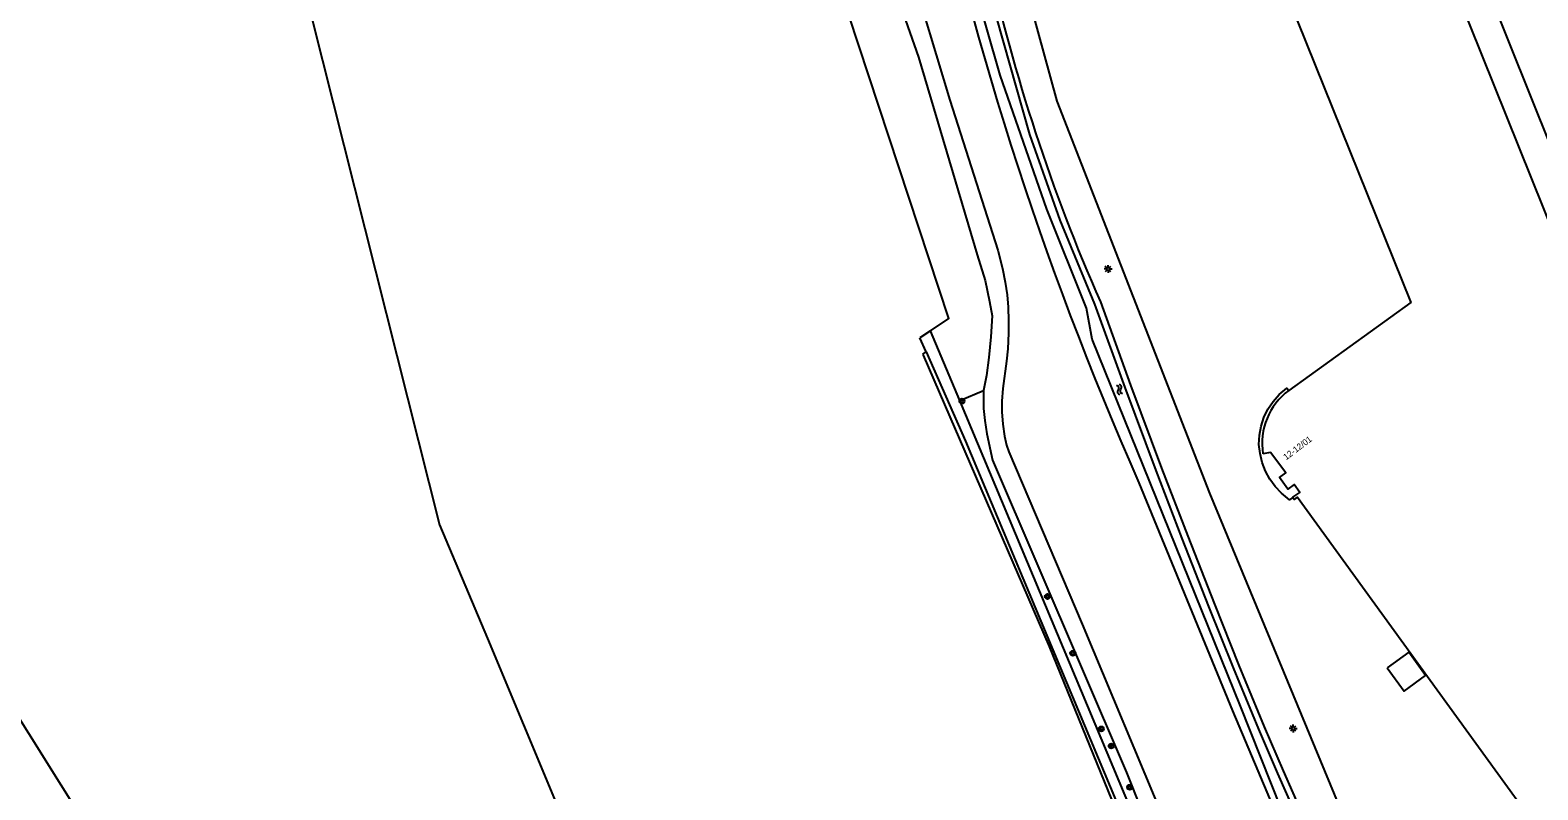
# Model space of a CAD drawing. Extents: x 126000 to 131009, y 393000 to 395500.
# Drawn here: x 130201.2 to 130441.7, y 393811.3 to 393932.5 of the extents above; entities that cross this region are included whole.
import ezdxf

# ---------------------------------------------------------------- set-up
doc = ezdxf.new("R2010")
doc.units = 0
for name, color, linetype in [('gg-afsc-hekwerk', 7, 'Continuous'), ('gg-anno-huisnummerreeks BGT', 7, 'Continuous'), ('gg-bbg-hoofdgebouw', 7, 'Continuous'), ('gg-bbg-luifel en loopbrug', 7, 'Continuous'), ('gg-bbg-onder overbouw', 7, 'Continuous'), ('gg-bbg-pand overbouw', 7, 'Continuous'), ('gg-knt-bovenkant onderkant talud', 7, 'Continuous'), ('gg-knt-onverhard', 7, 'Continuous'), ('gg-kntw-bovenkant insteek waterloop', 7, 'Continuous'), ('gg-kntw-waterlijn', 7, 'Continuous'), ('gt-grn-groengrens', 7, 'Continuous'), ('gt-grn-vlakafsluiter', 7, 'Continuous'), ('gt-symb-boom', 7, 'Continuous'), ('gt-symb-lichtmast', 7, 'Continuous'), ('gt-symb-watersymbool', 7, 'Continuous')]:
    doc.layers.add(name, color=color, linetype=linetype)

# ---------------------------------------------------------------- blocks, each defined once
blk = doc.blocks.new('gt0-BOOM')
at = {"layer": 'gt-symb-boom'}
for radius in [0.4, 0.2]:
    blk.add_circle((0, 0), radius, dxfattribs=at)
blk = doc.blocks.new('gt0-LMAST')
at = {"layer": 'gt-symb-lichtmast'}
for p, q in [((-0.18, 0.17), (-0.45, 0.44)), ((0, 0.25), (0, 0.62)), ((0.17, 0.17), (0.44, 0.44)), ((-0.25, 0), (-0.63, 0)), ((-0.18, -0.18), (-0.45, -0.45)), ((0, -0.25), (0, -0.63)), ((0.44, -0.45), (0.17, -0.18)), ((0.25, 0), (0.62, 0))]:
    blk.add_line(p, q, dxfattribs=at)
blk.add_circle((0, 0), 0.25, dxfattribs=at)
blk = doc.blocks.new('gt0-WA')
at = {"layer": 'gt-symb-watersymbool'}
for centre, start, end in [((-0.32, 0.02), 28.0725, 151.9275), ((0.43, 0.42), 208.0725, 331.9275), ((-0.32, -0.43), 28.0725, 151.9275), ((0.43, -0.03), 208.0725, 331.9275)]:
    blk.add_arc(centre, 0.425, start, end, dxfattribs=at)

msp = doc.modelspace()

# ---------------------------------------------------------------- linework, layer by layer
at = {"layer": 'gg-afsc-hekwerk'}
for points in [[(130518.08, 393804.24), (130450.49, 393897.35), (130417.4, 393979.8), (130452.86, 393994.13)], [(130352.16, 393970.02), (130352.22, 393969.57), (130355.72, 393955.06), (130364.98, 393921.2), (130389.33, 393858.66), (130441.55, 393732.61)], [(130241.04, 393954.79), (130266.48, 393853.63), (130274.14, 393835.51), (130309.16, 393751.6), (130325.51, 393722.7), (130367.54, 393647.87)], [(130241.04, 393954.79), (130266.48, 393853.63), (130274.14, 393835.51), (130309.16, 393751.6), (130325.51, 393722.7), (130367.54, 393647.87)], [(130418.52, 393694.74), (130420.33, 393695.5), (130363.81, 393834.2), (130343.72, 393880.68)]]:
    msp.add_lwpolyline(points, dxfattribs=at)
at = {"layer": 'gg-bbg-hoofdgebouw'}
msp.add_lwpolyline([(130402.64, 393858), (130402.88, 393857.66), (130403.39, 393858.03), (130459.16, 393781.07), (130504.62, 393814.17), (130446.66, 393894.17), (130413.01, 393977.88), (130389.49, 393968.43), (130421.42, 393889.08), (130401.98, 393875.06)], dxfattribs=at)
at = {"layer": 'gg-bbg-luifel en loopbrug'}
msp.add_lwpolyline([(130417.67, 393830.8), (130420.36, 393827.09), (130423.81, 393829.58), (130421.12, 393833.29), (130417.67, 393830.8)], dxfattribs=at)
at = {"layer": 'gg-bbg-onder overbouw'}
msp.add_lwpolyline([(130402.64, 393858), (130402.62, 393858.02), (130403.72, 393858.8), (130402.82, 393860.04), (130401.83, 393859.32), (130400.48, 393861.18), (130401.5, 393861.91), (130399.04, 393865.19), (130397.86, 393864.96)], dxfattribs=at)
msp.add_arc((130408.24, 393866.62), 10.51, 126.5555, 189.0808, dxfattribs=at)
at = {"layer": 'gg-bbg-pand overbouw'}
msp.add_lwpolyline([(130402.64, 393858), (130402.1, 393857.63), (130400.79, 393858.65), (130399.83, 393859.72), (130398.96, 393860.91), (130398.27, 393862.19), (130397.73, 393863.58), (130397.39, 393865.01), (130397.22, 393866.46), (130397.33, 393867.91), (130397.55, 393869.36), (130398, 393870.77), (130398.65, 393872.1), (130399.48, 393873.31), (130400.46, 393874.41), (130401.65, 393875.45), (130401.98, 393875.06)], dxfattribs=at)
at = {"layer": 'gg-knt-bovenkant onderkant talud'}
msp.add_lwpolyline([(130344.84, 393884.56), (130347.77, 393886.55), (130319.04, 393973.7)], dxfattribs=at)
at = {"layer": 'gg-knt-onverhard'}
for points in [[(130316.91, 393980.14), (130320.39, 393981.21), (130323.58, 393981.48), (130326.38, 393981.38), (130327.69, 393981.27), (130328.71, 393980.8), (130329.61, 393979.83), (130330.39, 393978.71), (130332.92, 393964.19), (130335.14, 393952.87), (130338.08, 393942.07), (130342.89, 393928.24), (130352.25, 393896.69), (130353.53, 393892.59), (130354.23, 393889.27), (130354.64, 393886.96), (130354.46, 393883.62), (130354.12, 393880.34), (130353.74, 393877.45), (130353.26, 393875.05)], [(130343.56, 393935.84), (130347.9, 393921.36), (130355.57, 393897.45), (130356.31, 393894.5), (130356.75, 393892.32), (130357.03, 393890.34), (130357.21, 393888.34), (130357.29, 393886.18), (130357.28, 393884.18), (130357.14, 393881.7), (130356.95, 393879.71), (130356.39, 393875.36), (130356.2, 393873.36), (130356.2, 393871.67), (130356.36, 393869.68), (130356.61, 393867.75), (130356.94, 393866.31), (130357.34, 393865.25), (130369, 393837.79), (130395.5, 393774.41), (130438.05, 393672.01), (130439.18, 393669.99), (130439.89, 393669.86)], [(130353.26, 393875.05), (130353.27, 393872.2), (130353.47, 393870.27), (130353.83, 393868.12), (130354.72, 393863.92), (130376.07, 393814.11), (130390.12, 393778.83), (130412.58, 393723.28), (130413.69, 393720.29)]]:
    msp.add_lwpolyline(points, dxfattribs=at)
at = {"layer": 'gg-kntw-bovenkant insteek waterloop'}
for p, q in [((130344.84, 393884.56), (130343.13, 393883.44)), ((130344.12, 393881.2), (130343.13, 393883.44)), ((130349.49, 393873.47), (130344.84, 393884.56)), ((130413.69, 393720.29), (130349.49, 393873.47))]:
    msp.add_line(p, q, dxfattribs=at)
for points in [[(130371.93, 393889.2), (130376.75, 393875.9), (130381.68, 393862.65), (130385.85, 393851.79), (130390.11, 393840.97), (130394.03, 393831.18), (130398.05, 393821.42), (130401.08, 393814.38), (130404.19, 393807.38), (130412.68, 393787.1), (130434.69, 393731.98)], [(130344.12, 393881.2), (130350.39, 393866.99), (130391.51, 393768.75), (130418.17, 393703.83), (130426, 393685.67), (130427.39, 393686.53)], [(130378.05, 393860.35), (130393.01, 393823.96), (130401.51, 393803.81), (130408.8, 393786.26), (130433.14, 393726.77)]]:
    msp.add_lwpolyline(points, dxfattribs=at)
for centre, radius, start, end in [((130869.85, 394077.19), 537.49, 191.5104, 203.7931), ((130638.73, 394007), 291.65, 192.4644, 203.823)]:
    msp.add_arc(centre, radius, start, end, dxfattribs=at)
at = {"layer": 'gg-kntw-waterlijn'}
for points in [[(130402.43, 393804.2), (130394.28, 393824.68), (130370.61, 393883.26), (130369.71, 393888.18), (130363.38, 393903.99), (130355.95, 393925.38), (130343.17, 393969.94)], [(130350.09, 393953.06), (130360.63, 393915.89), (130365.48, 393902.23), (130371, 393888.83), (130375.81, 393875.56), (130380.75, 393862.29), (130384.92, 393851.43), (130389.18, 393840.6), (130393.11, 393830.8), (130397.13, 393821.03), (130400.16, 393813.98), (130403.28, 393806.99)]]:
    msp.add_lwpolyline(points, dxfattribs=at)
at = {"layer": 'gt-grn-groengrens'}
msp.add_line((130349.49, 393873.47), (130353.26, 393875.05), dxfattribs=at)
msp.add_lwpolyline([(130221.53, 393797.79), (130211.29, 393803.86), (130195.8, 393828.6)], dxfattribs=at)
at = {"layer": 'gt-grn-vlakafsluiter'}
for q in [(130344.12, 393881.2), (130343.72, 393880.68)]:
    msp.add_line((130343.6, 393880.86), q, dxfattribs=at)

# ---------------------------------------------------------------- block references
at = {"layer": 'gt-symb-boom'}
for p in [(130349.84, 393873.36), (130363.48, 393842.19), (130367.53, 393833.14), (130372.06, 393821.07), (130373.66, 393818.34), (130376.61, 393811.76)]:
    msp.add_blockref('gt0-BOOM', p, dxfattribs=at)
at = {"layer": 'gt-symb-lichtmast'}
for p in [(130373.16, 393894.44), (130402.68, 393821.14)]:
    msp.add_blockref('gt0-LMAST', p, dxfattribs=at)
at = {"layer": 'gt-symb-watersymbool', "rotation": 109.88516511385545}
msp.add_blockref('gt0-WA', (130374.99, 393875.16), dxfattribs=at)

# ---------------------------------------------------------------- texts
at = {"layer": 'gg-anno-huisnummerreeks BGT'}
msp.add_text('12-12/01', height=1, rotation=36.9, dxfattribs=at).set_placement((130401.56, 393863.9))

doc.saveas('drawing.dxf')
